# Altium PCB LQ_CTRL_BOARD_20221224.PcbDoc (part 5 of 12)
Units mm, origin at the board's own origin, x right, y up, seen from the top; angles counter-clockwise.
Board outline 260 x 142 mm, 6 copper layers (Top Layer, Mid-Layer 1, Mid-Layer 2, Mid-Layer 3, Mid-Layer 4, Bottom Layer); 1105 components, 1039 nets, 3898 pads, 1277 vias.
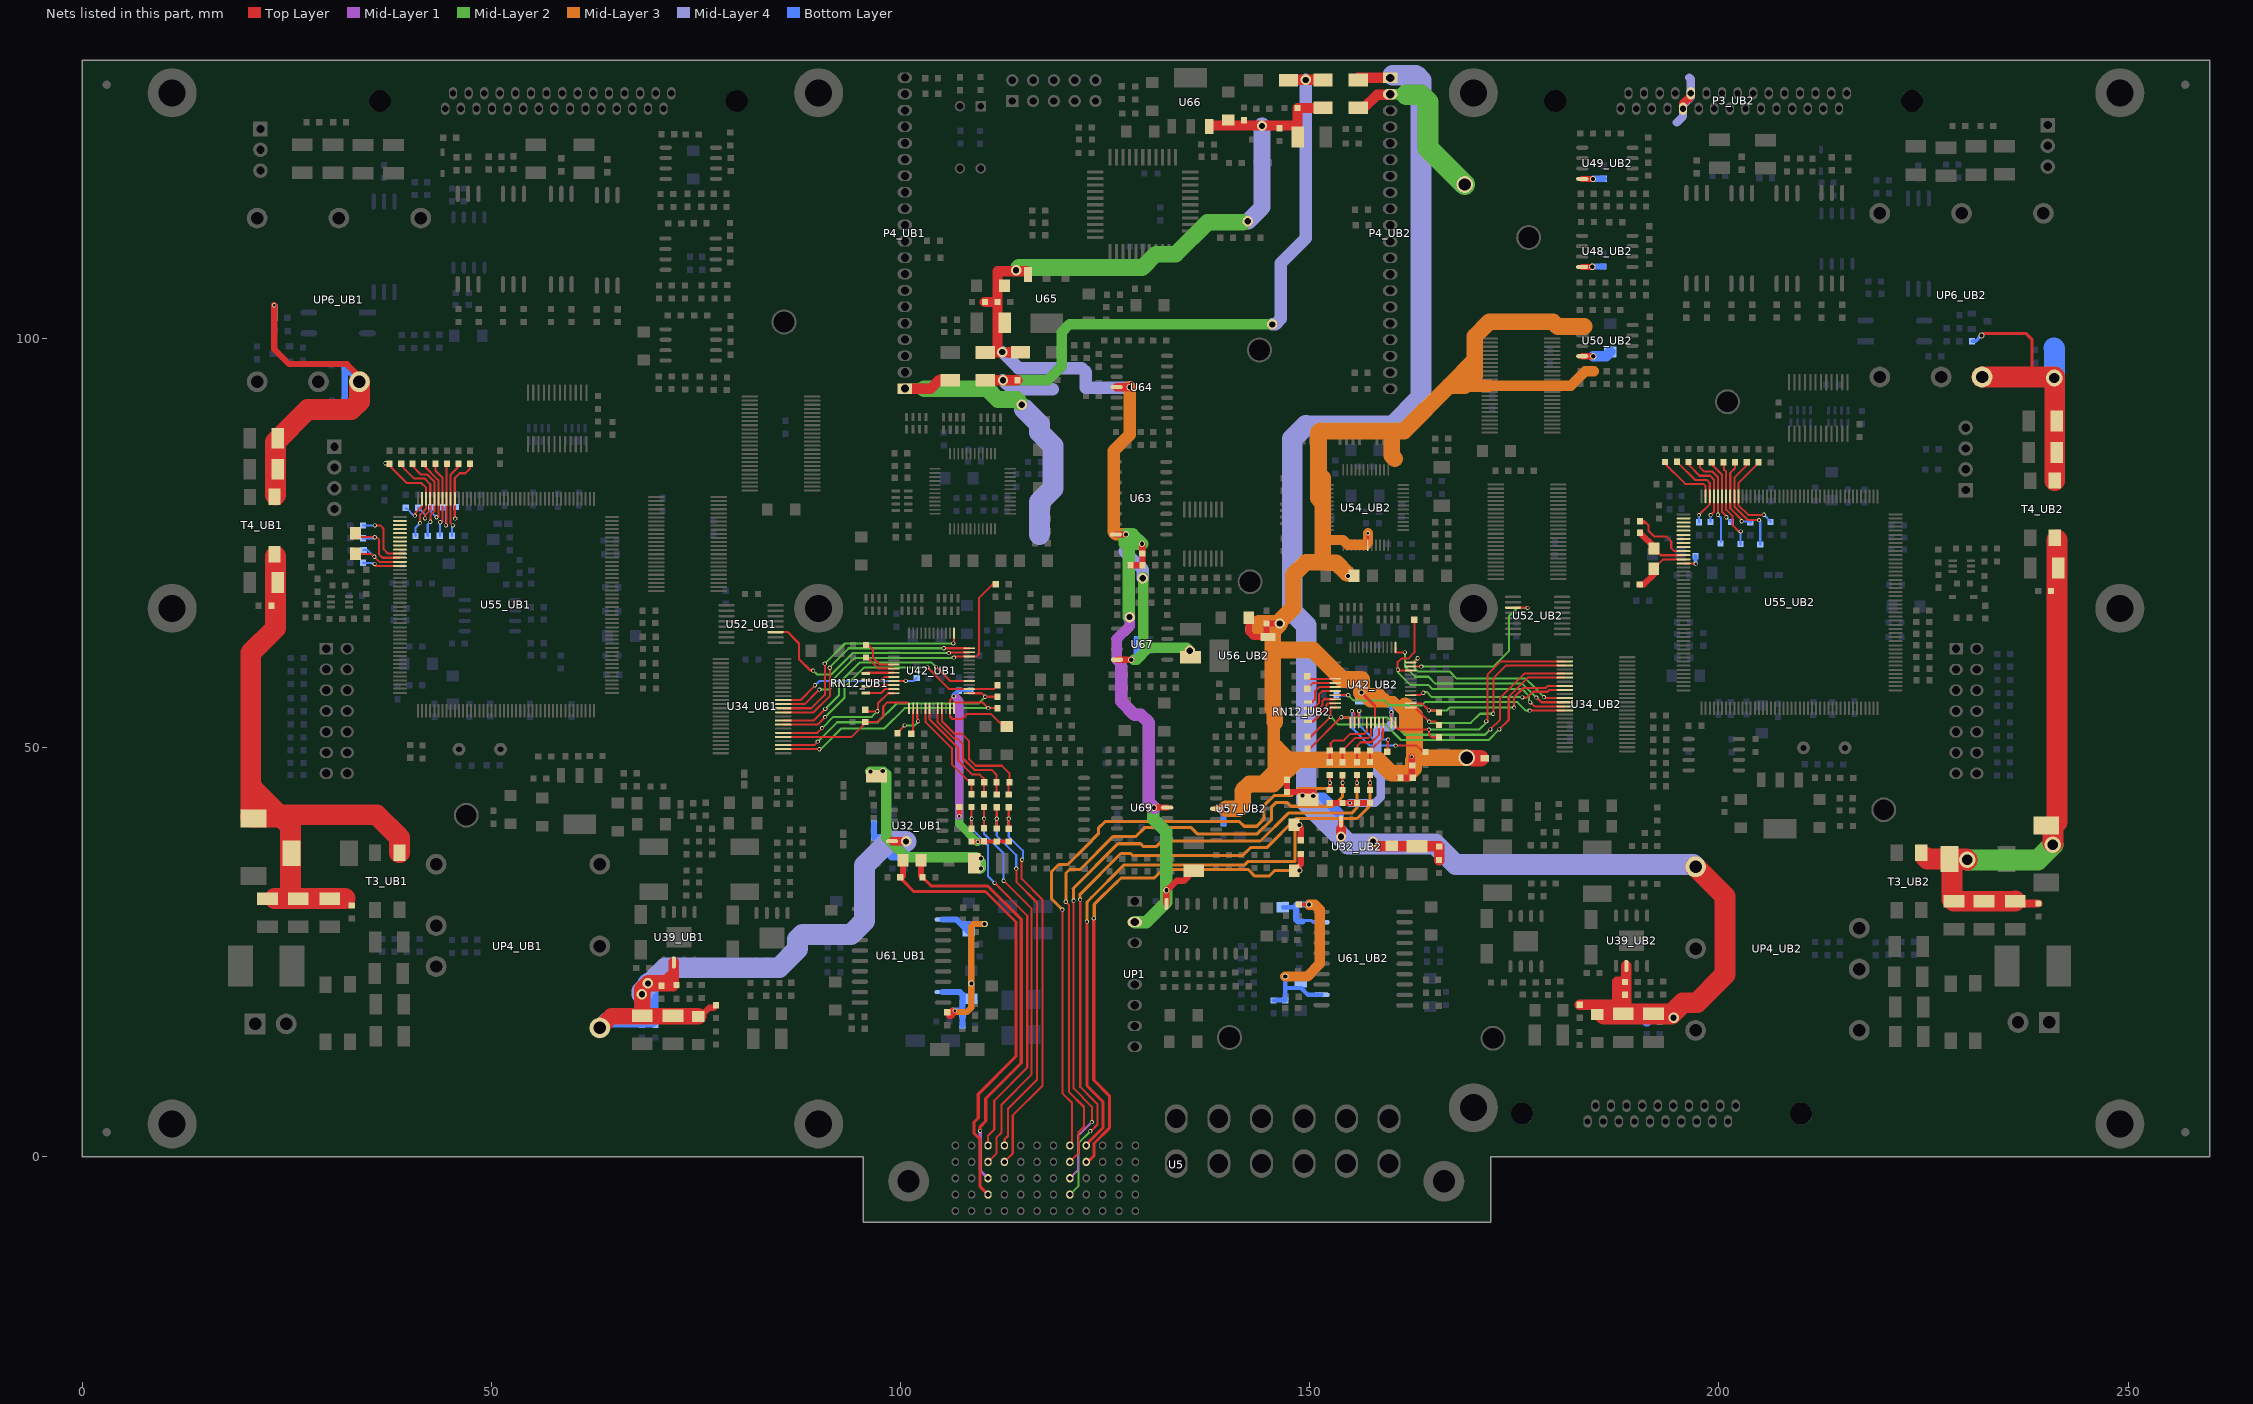
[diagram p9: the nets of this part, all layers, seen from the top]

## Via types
v1: diameter 0.508, hole 0.305, Top Layer to Bottom Layer, 845 vias
v2: diameter 0.762, hole 0.508, Top Layer to Bottom Layer, 317 vias
v3: diameter 1.27, hole 0.762, Top Layer to Bottom Layer, 77 vias
v4: diameter 2.032, hole 1.524, Top Layer to Bottom Layer, 15 vias
v5: diameter 2.032, hole 1.27, Top Layer to Bottom Layer, 11 vias
v6: diameter 1.27, hole 0.711, Top Layer to Bottom Layer, 8 vias
v7: diameter 2.54, hole 1.778, Top Layer to Bottom Layer, 3 vias
v8: diameter 1.524, hole 1.016, Top Layer to Bottom Layer, 1 vias

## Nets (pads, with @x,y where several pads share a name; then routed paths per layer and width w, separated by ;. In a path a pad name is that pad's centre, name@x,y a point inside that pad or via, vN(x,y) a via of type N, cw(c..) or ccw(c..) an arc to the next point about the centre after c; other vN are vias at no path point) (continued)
+5VA_UB2: C242_UB2.1 C284_UB2.1 C285_UB2.2 C311_UB2.1 C312_UB2.1 C327_UB2.1 C328_UB2.1 C373_UB2.1 C374_UB2.2 C393_UB2.1 C395_UB2.1 D28.1 P3_UB2.11 P3_UB2.26 P4_UB2.2 R203_UB2.1 R219_UB2.2 R229_UB2.2 R283_UB2.1 U42_UB2.43 U48_UB2.8 U49_UB2.8 U50_UB2.8 U54_UB2.43 U56_UB2.3 U57_UB2.4 | length 285.8
  Top Layer w0.254: C373_UB2.1@155.397,70.993 C373_UB2.1@155.397,71.17 ; v2(156.337,56.718) 157.984,55.072 U42_UB2.43@157.984,53.05 ; U54_UB2.43@157.092,74.723 157.092,75.978 157.074,75.996 157.074,76.123 v1(157.124,76.174) ; C242_UB2.1@162.535,47.803 162.535,46.361 R203_UB2.1@162.585,46.31
  Top Layer w0.762: U57_UB2.4@138.557,42.52 v2(139.776,42.52) ; C393_UB2.1@142.559,65.862 142.559,64.07 143.129,63.5 144.678,63.5 144.729,63.551 C395_UB2.1@144.729,65.151 146.325,65.151 v3@146.329,65.156 ; R219_UB2.2@160.985,46.31 162.484,46.31 162.535,46.361 162.484,46.412 v1(162.484,48.895) ; U48_UB2.8@183.286,108.717 184.511,108.717 v2(184.531,108.737) ; U50_UB2.8@183.312,97.815 v2(184.658,97.815) ; U49_UB2.8@183.312,119.482 v2(184.633,119.482)
  Top Layer w1.016: P3_UB2.26@195.621,128.047 195.621,128.685 196.573,129.637 P3_UB2.11@196.573,129.952
  Top Layer w1.27: D28.1@155.931,128.168 156.629,128.168 158.229,129.769 P4_UB2.2@159.646,129.769
  Top Layer w2.032: v4@169.875,48.692 R283_UB2.1@170.891,48.692
  Mid-Layer 2 w1.27: P4_UB2.2@159.842,129.826 161.766,129.826 161.823,129.769
  Mid-Layer 2 w2.54: 161.823,129.769 163.576,129.769 164.465,128.88 164.465,123.266 v4(168.935,118.796)
  Mid-Layer 3 w1.27: 151.587,75.362 154.051,75.362 154.635,74.778 156.896,74.778 157.124,75.006 v1(157.124,76.174) ; 159.309,55.677 160.198,55.677 161.544,54.331 161.544,52.426 162.814,51.156 ; 171.983,94.209 181.889,94.209 183.667,95.987 184.709,95.987
  Mid-Layer 3 w1.524: 143.916,45.542 145.618,47.244 145.618,50.241 ; 145.542,45.542 145.898,45.898 145.898,49.962 145.618,50.241 ; 145.721,53.087 145.618,52.984 145.618,50.241 ; 159.334,55.651 159.309,55.677 ; 168.935,94.209 171.983,94.209 ; 159.309,55.677 158.496,56.49 156.566,56.49 v2(156.337,56.718) 157.378,55.677 159.309,55.677
  Mid-Layer 3 w2.032: v2(139.776,42.52) 141.326,42.52 141.808,43.002 141.808,44.729 142.621,45.542 143.916,45.542 145.542,45.542 ; 143.104,64.44 143.815,65.151 145.491,65.151 ; 144.805,64.465 145.491,65.151 ; 145.721,53.087 145.721,54.482 145.593,54.61 145.542,54.61 145.466,54.686 145.466,61.62 ; 145.898,45.898 148.488,48.489 ; 145.898,49.962 147.371,48.489 148.488,48.489 ; 151.079,48.489 148.488,48.489 ; 151.587,82.931 151.587,79.934 ; v2@154.535,71.299 153.266,72.567 152.096,72.567 152.019,72.644 ; v2(156.337,56.718) 156.337,58.293 156.362,58.318 154.026,58.318 150.422,61.922 145.768,61.922 145.466,61.62 ; 160.401,85.268 160.02,85.649 160.02,88.671 ; 161.696,55.067 162.814,53.95 162.814,51.156 162.814,48.895 162.941,48.768 v4(169.189,48.768) 163.043,48.768 162.687,48.412 162.687,47.422 162.103,46.838 160.02,46.838 158.369,48.489 148.488,48.489 ; 170.18,97.384 170.18,97.333 ; 183.566,101.448 180.289,101.448 179.73,102.006 171.933,102.006 170.18,100.254 170.18,97.333 ; 145.466,61.62 145.466,64.262 ; 145.466,64.262 v3(146.355,65.151) v3@146.075,65.151 ; 145.466,64.262 145.466,64.541 v3@146.075,65.151 ; 145.491,65.151 v3@146.075,65.151 ; v3@146.075,65.151 147.98,67.056 147.98,71.095 149.53,72.644 152.019,72.644 ; 151.587,79.934 151.587,75.362 151.587,73.076 152.019,72.644 ; 151.587,79.934 151.079,80.442 151.079,88.519 151.232,88.671 160.02,88.671 ; 160.02,88.671 161.519,88.671 167.056,94.209 ; 167.056,94.209 170.18,97.333 ; 167.056,94.209 168.935,94.209 170.18,95.453 170.18,97.333
  Mid-Layer 4 w1.016: 194.869,126.365 195.621,127.117 P3_UB2.26@195.621,128.047 195.621,128.54 196.573,129.492 P3_UB2.11@196.573,129.952 196.573,131.671 196.367,131.877
  Bottom Layer w0.762: C327_UB2.1@139.471,40.73 139.471,42.215 v2(139.776,42.52) 141.351,42.52 C284_UB2.1@141.427,42.596 ; C328_UB2.1@154.381,57.836 154.635,57.582 155.905,57.582 156.312,57.175 C312_UB2.1@156.312,56.007 ; v2(184.531,108.737) 184.556,108.763 C374_UB2.2@185.903,108.763 ; v2(184.633,119.482) 184.658,119.507 C285_UB2.2@185.928,119.507
  Bottom Layer w1.27: v2(184.658,97.815) 186.221,97.815 186.741,98.336 C311_UB2.1@186.741,98.349
  other v2: 154.686,70.967
+5VMS: C3.1 C4.1 C428.1 C429.1 C430.1 C431.1 C432.1 C434.1 C436.1 C438.1 C444.1 D27.2 D28.2 DR4.1 LED17.1 R399.1 R406.2 U2.8 U63.16 U64.4 U65.3 U66.3 U69.4 UP1.2 | length 194.2
  Top Layer w0.762: U63.16@126.314,76.022 127.305,76.022 v2@127.33,76.048 ; R406.2@128.092,72.259 129.544,72.259 R399.1@129.56,72.275 129.56,73.697 C444.1@129.535,73.723 129.535,74.823 v2@129.54,74.828 ; v2@130.962,42.672 130.975,42.659 U69.4@132.593,42.659 ; v2@132.486,32.614 132.486,30.912 U2.8@132.512,30.886 132.512,32.639 132.664,32.639 133.756,33.731 134.645,33.731 C3.1@135.839,34.925
  Top Layer w1.016: U64.4@126.416,94.031 127.914,94.031 127.94,94.056 127.965,94.031 v2(127.991,94.031)
  Top Layer w1.27: C434.1@110.312,104.445 C430.1@111.851,104.445 ; D27.2@110.37,98.273 v3@111.912,98.273 ; 111.851,107.899 C430.1@111.851,104.445 ; 111.862,108.204 U65.3@115.403,108.204 ; 113.36,98.222 113.309,98.273 ; DR4.1@114.656,98.298 113.335,98.298 113.309,98.273 ; U66.3@138.125,126.009 148.336,126.009 148.514,126.187 ; C428.1@148.539,124.612 148.514,124.638 148.514,126.187 ; D28.2@151.631,128.168 151.605,128.143 LED17.1@148.514,128.143 148.514,126.187 ; C430.1@111.851,104.445 111.851,98.334 v3@111.912,98.273 ; v3@111.912,98.273 113.309,98.273
  Mid-Layer 1 w1.27: 126.975,59.868 126.975,60.173 126.441,60.706 126.441,63.297 127.991,64.846 v3(127.991,65.938)
  Mid-Layer 1 w1.524: 126.975,59.868 126.975,55.631 128.605,54 129.388,54 130.353,53.035 130.353,43.282 v2(130.988,42.647)
  Mid-Layer 2 w1.524: v3@127.889,65.938 127.889,74.905 ; UP1.2@128.626,28.677 130.048,28.677 132.486,31.115 132.486,39.675 130.912,41.25 130.912,42.57 v2(130.988,42.647) ; 127.432,74.93 127.432,75.921 v2(127.559,76.048) 128.372,76.048 v2(129.515,74.905) 127.457,74.905 127.432,74.93
  Mid-Layer 2 w2.032: v3@114.44,108.648 129.553,108.648 131.191,110.287 133.629,110.287 137.516,114.173 v3@141.834,114.173
  Mid-Layer 3 w1.524: v2(127.559,76.048) 126.34,76.048 126.035,76.352 126.035,86.258 127.991,88.214 v2(127.991,94.031)
  Mid-Layer 4 w1.524: v3(112.446,98.323) 114.402,96.368 122.149,96.368 122.657,95.86 122.657,93.955 127.914,93.955 v2(127.991,94.031)
  Mid-Layer 4 w2.032: v3@142.456,114.287 144.17,116.002 v3(144.17,125.959)
  Bottom Layer w0.762: UP1.2@128.575,28.626 UP1.2@128.626,28.677 130.429,28.677 131.191,29.439 C4.1@131.191,29.667
  other v2: 132.486,32.563
  other v3: 114.122,108.331 142.443,114.3
+12V_UB1: C16_UB1.1 C233_UB1.1 C234_UB1.2 C235_UB1.2 C263_UB1.1 C264_UB1.2 C286_UB1.1 C287_UB1.1 C288_UB1.1 C289_UB1.1 C377_UB1.1 C378_UB1.1 C379_UB1.1 D25.1 LED9_UB1.1 P4_UB1.1 R236_UB1.1 U32_UB1.8 U39_UB1.2 UP4_UB1.3 | length 152.2
  Top Layer w0.762: C263_UB1.1@75.311,17.145 75.565,17.145 76.632,18.212 77.165,18.212 LED9_UB1.1@77.47,18.517
  Top Layer w1.016: U32_UB1.8@98.973,38.557 v3@100.381,38.557
  Top Layer w1.27: 71.577,21.793 72.085,22.301 ; R236_UB1.1@72.263,20.828 72.314,20.879 U39_UB1.2@72.314,23.749 ; P4_UB1.1@100.533,93.853 103.708,93.853 104.826,94.971 ; D25.1@105.842,94.869 D25.1@106.07,94.869
  Top Layer w2.032: UP4_UB1.3@63.262,15.745 64.662,17.145 C263_UB1.1@75.311,17.145 ; C16_UB1.1@68.453,17.221 68.453,20.472 69.19,21.209 71.806,21.209
  Mid-Layer 2 w1.27: v2(96.317,47.066) 97.917,47.066 98.247,46.736 98.247,39.014 100.686,36.576 109.22,36.576 109.83,35.966 v2(109.83,35.23) ; P4_UB1.1@100.533,93.853 102.921,93.853
  Mid-Layer 2 w2.032: 102.921,93.853 110.56,93.853 111.881,92.532 114.198,92.532 v3@114.529,92.202
  Mid-Layer 4 w2.54: v3(68.402,19.863) 68.402,20.218 71.272,23.089 85.141,23.089 87.427,25.375 87.427,26.568 88.011,27.153 93.955,27.153 95.606,28.804 95.606,35.585 98.552,38.532 v3(100.686,38.532) ; 115.164,91.338 116.992,89.51 116.992,88.519 118.643,86.868 118.643,81.661 116.992,80.01 116.992,76.048
  Bottom Layer w0.762: C287_UB1.1@96.774,40.716 C286_UB1.1@96.774,39.04 99.898,39.04 v3@100.381,38.557
  Bottom Layer w1.27: C377_UB1.1@98.984,36.805 C378_UB1.1@100.508,36.805 100.508,38.43 v3@100.381,38.557
  Bottom Layer w2.032: UP4_UB1.3@63.262,15.745 63.268,15.745 64.338,16.815 69.52,16.815
  Bottom Layer w2.54: 69.139,17.17 v3(69.139,21.184)
  other v2: 109.823,36.437 97.841,47.117
  other v3: 114.808,91.872
+12V_UB2: C16_UB2.1 C233_UB2.1 C234_UB2.2 C235_UB2.2 C263_UB2.1 C264_UB2.2 C286_UB2.1 C287_UB2.1 C288_UB2.1 C289_UB2.1 C377_UB2.1 C378_UB2.1 C379_UB2.1 D26.1 LED9_UB2.1 P4_UB2.1 R236_UB2.1 U32_UB2.8 U39_UB2.2 UP4_UB2.3 | length 251.6
  Top Layer w0.762: C377_UB2.1@147.244,46.076 C378_UB2.1@147.244,44.552 150.495,44.552 150.52,44.526 150.52,44.348 C379_UB2.1@149.784,43.612 ; 153.822,40.03 U32_UB2.8@153.822,40.97
  Top Layer w1.27: v3(153.822,39.091) 153.822,40.03 ; D26.1@155.931,131.826 P4_UB2.1@159.842,131.826 ; v3@157.785,38.456 158.318,37.922 C289_UB2.1@160.096,37.922 ; C289_UB2.1@160.02,37.998 C289_UB2.1@160.096,37.922 ; C286_UB2.1@165.811,36.246 165.811,37.897 C287_UB2.1@165.837,37.922 C288_UB2.1@163.119,37.922 C289_UB2.1@160.096,37.922 ; LED9_UB2.1@183.007,18.567 187.122,18.567 ; C263_UB2.1@185.191,17.45 186.004,17.45 187.122,18.567 ; C16_UB2.1@188.316,17.45 188.697,17.831 188.697,19.152 ; R236_UB2.1@188.519,21.361 187.604,21.361 187.604,19.05 187.122,18.567 ; U39_UB2.2@188.697,23.317 188.697,19.152 ; 187.122,18.567 188.112,18.567 188.697,19.152
  Top Layer w2.54: 186.004,17.45 C16_UB2.1@188.316,17.45 C233_UB2.1@192.024,17.45 194.234,17.45 195.605,18.821 197.333,18.821 200.762,22.25 200.762,31.825 UP4_UB2.3@197.15,35.436
  Mid-Layer 4 w2.54: P4_UB2.1@160.198,132.156 161.62,132.156 ; UP4_UB2.3@197.15,35.436 196.874,35.712 167.843,35.712 165.329,38.227 154.686,38.227 v3(153.822,39.091) 149.581,43.332 149.581,64.907 147.879,66.608 147.879,87.706 149.555,89.383 149.631,89.306 160.147,89.306 163.601,92.761 163.601,130.175 ; 161.62,132.156 163.601,130.175 ; 161.62,132.156 162.97,132.156 163.601,131.525 163.601,130.175
  Bottom Layer w0.762: 153.213,40.64 153.213,41.758 151.435,43.536 149.174,43.536 149.123,43.586 v2(149.123,44.145) 151.74,44.145 153.822,42.062 153.822,40.03 ; 153.213,40.64 153.822,40.03 ; 153.213,40.64 153.213,39.7 v3(153.822,39.091) 153.822,40.03
  Bottom Layer w1.27: C235_UB2.2@191.186,16.535 191.186,16.916 v3@194.107,16.916
  other v2: 150.444,44.094
  other v3: 194.462,16.993 157.734,38.481
+12VMS: C424.1 C425.1 C426.1 D25.2 D26.2 DR3.1 LED16.1 U67.8 | length 109.9
  Top Layer w0.762: U67.8@126.461,60.731 v2(128.194,60.731)
  Top Layer w1.27: D25.2@110.37,94.869 v3(112.522,94.869) LED16.1@114.3,94.869 ; C424.1@135.204,61.57 135.433,61.341 C424.1@135.433,61.011 ; DR3.1@148.285,131.521 148.336,131.572 v3(149.53,131.572) D26.2@151.631,131.572
  Mid-Layer 2 w1.27: v3(112.522,94.869) 118.008,94.869 119.71,96.571 119.71,100.762 120.65,101.702 138.684,101.702 ; v2@128.473,60.731 128.854,60.731 130.302,62.179 ; v3@129.642,70.79 129.642,62.84 130.302,62.179 ; v3(135.357,61.824) 135.001,62.179 130.302,62.179 ; 138.709,101.727 138.684,101.702 ; v3(145.415,101.702) 138.684,101.702
  Mid-Layer 4 w1.524: v3(112.522,94.869) 113.614,93.777 118.593,93.777 ; 127.381,73.965 129.616,71.73 v3(129.616,70.688) ; v3(145.415,101.702) 145.796,101.702 146.456,102.362 146.456,109.169 149.53,112.243 v3(149.53,131.572)
  Bottom Layer w0.762: v2(128.194,60.731) 128.473,60.731 128.88,61.138 C425.1@128.88,63.246
+28V_UB1: C214_UB1.1 C221_UB1.1 C222_UB1.1 C223_UB1.1 C276_UB1.1 C277_UB1.2 D13_UB1.2 DR2_UB1.1 T3_UB1.4 T4_UB1.2 | length 82.1
  Top Layer w2.54: D13_UB1.2@20.584,41.504 24.333,41.504 24.054,41.783 ; 20.599,46.126 20.599,42.545 21.361,41.783 24.054,41.783 ; 20.599,46.203 20.599,61.544 23.627,64.572 T4_UB1.2@23.627,73.381 ; 20.828,45.136 20.828,45.009 24.054,41.783 ; C222_UB1.1@23.546,31.547 C221_UB1.1@26.416,31.547 C223_UB1.1@30.251,31.547 32.121,31.547 ; 24.496,41.341 25.146,40.691 25.146,41.783 ; C221_UB1.1@25.451,31.521 25.451,40.665 ; T3_UB1.4@38.789,37.15 38.789,38.986 35.992,41.783 25.146,41.783 ; 24.054,41.783 25.146,41.783
+28V_UB2: C214_UB2.1 C221_UB2.1 C222_UB2.1 C223_UB2.1 C276_UB2.1 C277_UB2.2 D13_UB2.2 DR2_UB2.1 T3_UB2.4 T4_UB2.2 | length 69.3
  Top Layer w1.016: C221_UB2.1@236.22,31.242 236.525,30.937 C277_UB2.2@239.039,30.937
  Top Layer w2.54: T3_UB2.4@225.294,36.572 225.494,36.373 DR2_UB2.1@228.168,36.373 DR2_UB2.1@228.473,36.373 ; v5(230.327,36.271) 230.226,36.373 DR2_UB2.1@228.473,36.373 ; C221_UB2.1@236.22,31.242 236.195,31.217 C222_UB2.1@228.727,31.217 228.473,31.471 DR2_UB2.1@228.473,36.373 ; v5@240.868,38.354 240.843,38.379 240.843,40.401 241.325,40.884 T4_UB2.2@241.325,75.352
  Mid-Layer 2 w2.54: v5(230.327,36.271) 238.963,36.271 v5(240.817,38.125)
+28VB_UB1: C269_UB1.2 C270_UB1.1 C271_UB1.1 C272_UB1.2 R256_UB1.2 T4_UB1.1 UP6_UB1.2 | length 47.4
  Top Layer w0.762: v1(23.47,104.038) 23.47,98.679 25.298,96.85 32.334,96.85 33.885,95.299 UP6_UB1.2@33.885,94.691
  Top Layer w2.54: T4_UB1.1@23.622,80.848 23.622,87.325 27.584,91.288 ; 27.61,91.313 27.584,91.288 ; UP6_UB1.2@33.885,94.691 33.885,92.28 32.893,91.288 27.584,91.288
  Bottom Layer w0.762: v1(23.47,104.038) 23.495,104.013 R256_UB1.2@23.495,102.514 ; C269_UB1.2@32.055,96.698 32.106,96.647 C269_UB1.2@32.106,96.471 ; C272_UB1.2@32.106,92.405 C269_UB1.2@32.106,96.471 ; UP6_UB1.2@33.885,94.691 C269_UB1.2@32.106,96.471
+28VB_UB2: C269_UB2.2 C270_UB2.1 C271_UB2.1 C272_UB2.2 R256_UB2.2 T4_UB2.1 UP6_UB2.2 | length 37.8
  Top Layer w0.381: v2(232.08,100.355) 232.334,100.609 237.49,100.609 238.277,99.822 238.277,95.275
  Top Layer w2.54: UP6_UB2.2@232.158,95.275 238.277,95.275 241.051,95.275 T4_UB2.1@241.051,82.626
  Bottom Layer w0.381: R256_UB2.2@230.937,99.644 231.369,99.644 v2(232.08,100.355)
  Bottom Layer w2.54: 240.944,98.806 240.995,98.755 v5(240.995,95.148)
+CAN5V_UB1: C11_UB1.1 C410_UB1.1 C411_UB1.1 C412_UB1.1 LED15_UB1.1 U61_UB1.12 U61_UB1.19 | length 31.2
  Top Layer w0.762: 105.918,17.196 106.172,17.196 106.401,17.424 v1@106.401,17.856
  Mid-Layer 3 w0.762: v1@106.401,17.856 106.578,17.678 108.102,17.678 108.636,18.212 108.636,20.98 108.636,28.169 108.89,28.423 v2(110.287,28.423)
  Bottom Layer w0.762: U61_UB1.19@105.161,20.117 107.239,20.117 107.564,19.792 C410_UB1.1@107.564,17.475 ; U61_UB1.12@105.161,28.981 106.858,28.981 107.417,28.423 ; v1(106.604,17.856) 107.386,17.856 ; 107.183,17.856 C410_UB1.1@107.564,17.475 ; C412_UB1.1@107.564,16.027 C410_UB1.1@107.564,17.475 ; C410_UB1.1@107.589,17.45 C410_UB1.1@107.564,17.475 ; C11_UB1.1@108.356,27.483 107.417,28.423 ; C411_UB1.1@108.636,19.329 v2@108.636,20.98 ; v2(110.287,28.423) 107.417,28.423
  other v2: 108.661,21.158
+CAN5V_UB2: C11_UB2.1 C410_UB2.1 C411_UB2.1 C412_UB2.1 LED15_UB2.1 U61_UB2.12 U61_UB2.19 | length 32.7
  Top Layer w0.381: LED15_UB2.1@148.655,30.81 v2(149.936,30.81)
  Mid-Layer 3 w1.27: v2(147.015,22.022) 149.682,22.022 151.232,23.571 151.232,30.175 150.597,30.81 v2(149.936,30.81)
  Bottom Layer w0.381: 149.115,28.736 149.233,28.854 150.241,28.854 150.444,28.651 U61_UB2.19@151.449,28.651
  Bottom Layer w0.508: C412_UB2.1@145.567,19.101 C410_UB2.1@147.015,19.101 147.015,20.625 ; 145.974,19.177 C410_UB2.1@146.724,19.177 ; C11_UB2.1@146.736,30.48 148.045,30.48 148.325,30.201 ; 146.964,20.625 147.015,20.625 ; v2(147.015,22.022) 147.015,20.625 ; 149.115,28.736 149.123,28.727 ; U61_UB2.12@151.449,19.787 149.809,19.787 148.971,20.625 147.015,20.625
  Bottom Layer w0.762: 149.115,28.736 148.607,28.736 148.361,28.981 148.361,30.164 148.325,30.201 148.325,30.672 148.463,30.81 v2(149.936,30.81)
A_COS+: R217_UB1.1 R220_UB1.2 U5.D4 | length 48.2
  Top Layer w0.254: U5.D4@112.7,-0.627 113.716,0.389 113.716,5.055 117.348,8.687 117.348,31.414 114.808,33.954 v1@114.808,36.297 ; R217_UB1.1@113.222,42.697 113.233,42.687 v1(113.233,41.326) R220_UB1.2@113.233,40.081
  Bottom Layer w0.254: v1(113.233,41.326) 113.233,39.116 114.96,37.389 v1@114.96,36.398
  other v1: 114.859,36.297
A_COS+'_UB1: C251_UB1.2 R217_UB1.2 U42_UB1.45 | length 16.4
  Top Layer w0.254: U42_UB1.45@105.049,54.785 105.049,53.242 106.602,51.689 107.467,51.689 108.382,50.775 108.382,48.571 109.176,47.777 112.395,47.777 113.309,46.863 C251_UB1.2@113.309,45.745 113.222,45.658 R217_UB1.2@113.222,44.272
A_COS+'_UB2: C251_UB2.2 R217_UB2.2 U42_UB2.45 | length 5.7
  Top Layer w0.254: R217_UB2.2@157.378,48.082 C251_UB2.2@157.378,49.649 157.421,49.649 158.984,51.211 U42_UB2.45@158.984,53.05
A_COS+_UB2: R217_UB2.1 R220_UB2.2 U5.B8 | length 83.8
  Top Layer w0.254: v1@121.971,31.42 121.971,8.534 123.406,7.099 124.079,6.426 124.079,3.937 123.266,3.124 v1(123.215,3.124) ; R220_UB2.2@157.378,44.798 R217_UB2.1@157.378,46.66
  Mid-Layer 2 w0.254: U5.B8@120.7,-4.627 121.742,-3.585 121.742,1.651 v1(123.215,3.124)
  Mid-Layer 3 w0.381: v1(121.945,31.42) 121.945,32.08 126.924,37.059 128.118,37.059 128.359,36.817 141.821,36.817 142.773,37.77 144.755,37.77 148.311,41.326 155.804,41.326 157.391,42.913 v1(157.391,45.72)
A_COS-: R225_UB1.2 R228_UB1.1 U5.E4 | length 46.5
  Top Layer w0.254: R228_UB1.1@111.749,42.697 111.76,42.687 v1(111.76,41.3) R225_UB1.2@111.76,40.107 ; U5.E4@112.878,1.55 U5.E4@112.7,1.373 112.7,2.108 113.132,2.54 113.132,5.842 116.688,9.398 116.688,31.064 114.198,33.553 114.198,35.027 v1@114.021,35.204
  Bottom Layer w0.254: v1(111.76,41.3) 111.76,39.243 114.148,36.855 v1(114.148,35.204)
A_COS-'_UB1: C251_UB1.1 R228_UB1.2 U42_UB1.44 | length 15
  Top Layer w0.254: U42_UB1.44@104.549,54.785 104.549,53.095 106.565,51.079 106.985,51.079 107.645,50.419 107.645,48.661 109.043,47.263 111.157,47.263 111.735,46.685 C251_UB1.1@111.735,45.745 111.749,45.731 R228_UB1.2@111.749,44.272
A_COS-'_UB2: C251_UB2.1 R228_UB2.2 U42_UB2.44 | length 6.9
  Top Layer w0.254: R228_UB2.2@155.778,48.057 155.778,49.624 C251_UB2.1@155.804,49.649 155.829,49.675 155.829,50.241 156.235,50.648 157.556,50.648 158.484,51.575 U42_UB2.44@158.484,53.05
A_COS-_UB2: R225_UB2.2 R228_UB2.1 U5.C8 | length 82.5
  Top Layer w0.254: v1(121.158,31.293) 121.158,8.357 123.393,6.121 v1(123.393,4.242) ; R225_UB2.2@155.778,44.806 R228_UB2.1@155.778,46.634
  Mid-Layer 1 w0.254: U5.C8@120.7,-2.627 121.717,-1.61 121.717,2.565 ; 122.111,2.959 121.717,2.565 ; v1(123.393,4.242) 121.717,2.565
  Mid-Layer 3 w0.381: 121.082,32.766 121.158,32.842 ; v1(121.158,31.293) 121.158,32.842 ; 121.526,33.21 121.158,32.842 ; v1(155.766,45.695) 155.766,42.608 155.143,41.986 147.396,41.986 143.993,38.583 131.928,38.583 131.242,37.897 129.692,37.897 129.35,38.24 126.555,38.24 121.158,32.842
A_E\X\C\_UB1: C248_UB1.2 U42_UB1.39 | length 4.9
  Top Layer w0.254: C248_UB1.2@99.644,51.74 99.644,51.841 v1(100.508,52.705) ; U42_UB1.39@102.049,54.785 102.049,53.552 102.159,53.442 v1(102.159,53.188)
  Mid-Layer 2 w0.254: v1(100.508,52.705) 101.727,52.705 102.184,53.162 v1(102.159,53.188)
A_E\X\C\_UB2: C248_UB2.2 U42_UB2.39 | length 9
  Top Layer w0.254: U42_UB2.39@155.984,53.05 155.984,54.395 v1(156.058,54.469) ; C248_UB2.2@159.537,49.454 159.537,50.927 v1(159.588,50.978)
  Bottom Layer w0.254: v1(156.058,54.469) 156.058,52.73 157.81,50.978 v1(159.588,50.978)
A_EXC_UB1: C225_UB1.2 U42_UB1.38 | length 3.2
  Top Layer w0.254: C225_UB1.2@101.321,51.689 101.549,51.917 U42_UB1.38@101.549,54.785
A_EXC_UB2: C225_UB2.2 U42_UB2.38 | length 13.5
  Top Layer w0.254: v1@155.143,54.432 155.484,54.092 U42_UB2.38@155.484,53.05 ; v1(160.503,50.241) 163.068,50.241 C225_UB2.2@163.855,49.454
  Bottom Layer w0.254: v1(155.169,54.458) 155.169,52.4 157.328,50.241 v1(160.503,50.241)
A_EXCN: C250_UB1.1 R216_UB1.1 U5.B3 | length 55.3
  Top Layer w0.381: R216_UB1.1@100.305,34.301 100.203,34.199 100.203,33.833 101.625,32.41 110.388,32.41 114.122,28.677 114.122,12.268 109.499,7.645 109.499,4.724 108.966,4.191 108.966,2.896 109.728,2.134 109.728,-3.655 ; 109.728,-3.2 109.728,-3.655 ; U5.B3@110.7,-4.627 109.728,-3.655
  Top Layer w0.762: R216_UB1.1@100.058,34.054 R216_UB1.1@100.203,34.199 ; R216_UB1.1@100.305,34.301 C250_UB1.1@100.305,36.22
A_EXCN_UB2: C250_UB2.1 R216_UB2.1 U5.E9 | length 66.2
  Top Layer w0.381: U5.E9@122.7,1.373 122.7,1.491 124.739,3.531 124.739,6.731 122.784,8.687 v1(122.784,28.727)
  Top Layer w0.762: C250_UB2.1@148.082,40.589 148.463,40.589 148.895,40.157 R216_UB2.1@148.895,38.659
  Mid-Layer 3 w0.381: v1(122.784,28.727) 122.784,31.115 123.215,31.547 ; 123.355,31.686 123.215,31.547 ; v2(148.742,40.538) 148.184,39.98 148.184,36.093 142.494,36.093 142.062,35.662 127.33,35.662 123.215,31.547
A_EXCP: C224_UB1.1 R198_UB1.2 U5.C3 | length 51.2
  Top Layer w0.381: R198_UB1.2@102.692,34.163 103.784,33.071 110.693,33.071 114.757,29.007 114.757,11.455 110.414,7.112 110.414,4.369 109.728,3.683 v1(109.728,3.15)
  Top Layer w0.762: C224_UB1.1@102.504,36.246 102.504,34.352 R198_UB1.2@102.692,34.163
  Mid-Layer 1 w0.381: 109.753,-1.016 109.753,-1.681 ; v1@109.753,3.251 109.753,-1.681 ; U5.C3@110.7,-2.627 109.753,-1.681
A_EXCP_UB2: C224_UB2.1 R198_UB2.2 U5.D9 | length 63.7
  Top Layer w0.381: U5.D9@122.7,-0.627 122.893,-0.627 123.647,0.127 123.647,1.612 125.527,3.492 125.527,7.468 123.622,9.373 v1(123.622,29.116)
  Top Layer w0.762: C224_UB2.1@148.107,34.95 148.92,35.763 R198_UB2.2@148.92,36.982
  Mid-Layer 3 w0.381: v1@123.673,29.159 123.673,30.836 126.467,33.63 126.517,33.63 ; 126.238,33.35 126.949,34.061 131.015,34.061 131.559,34.606 131.559,34.608 132.029,35.077 142.519,35.077 143.307,34.29 145.034,34.29 145.72,34.976 v2(148.768,34.976)
A_RDC_A0_UB1: R280_UB1.1 U34_UB1.5 U42_UB1.37 | length 18.2
  Top Layer w0.254: U34_UB1.5@85.674,51.301 85.681,51.308 94.031,51.308 R280_UB1.1@95.58,52.857 ; R280_UB1.1@95.707,53.111 97.13,53.111 97.892,53.873 97.892,55.016 98.4,55.524 100.838,55.524 101.049,55.314 U42_UB1.37@101.049,54.785
A_RDC_A0_UB2: R280_UB2.1 U34_UB2.5 U42_UB2.37 | length 40.3
  Top Layer w0.254: R280_UB2.1@149.733,49.86 149.987,49.86 153.822,53.696 v1(153.873,53.696) 154.915,53.696 154.984,53.627 U42_UB2.37@154.984,53.05 ; v1(172.085,52.222) 173.279,53.416 173.279,56.083 176.232,59.036 U34_UB2.5@181.178,59.036
  Mid-Layer 2 w0.254: v1(153.873,53.696) 159.487,53.696 161.62,51.562 171.425,51.562 v1(172.085,52.222)
A_RDC_A1_UB1: R281_UB1.1 U34_UB1.6 U42_UB1.36 | length 17.5
  Top Layer w0.254: U34_UB1.6@85.674,51.801 89.851,51.801 v1(90.424,52.375) ; R281_UB1.1@95.773,54.419 97.244,54.419 97.244,55.385 98.494,56.635 U42_UB1.36@99.199,56.635
  Mid-Layer 2 w0.254: v1(90.424,52.375) 91.796,53.746 96.495,53.746 v1(97.18,54.432)
A_RDC_A1_UB2: R281_UB2.1 U34_UB2.6 U42_UB2.36 | length 41.8
  Top Layer w0.254: R281_UB2.1@149.733,51.359 150.165,51.359 v1(152.552,53.746) 152.552,54.889 152.563,54.9 U42_UB2.36@153.134,54.9 ; v1(173.177,52.222) 174.32,53.365 ; 174.32,55.016 174.32,53.365 ; U34_UB2.6@181.178,58.536 176.65,58.536 174.32,56.206 174.32,53.365
  Mid-Layer 2 w0.254: v1(152.552,53.746) 153.492,52.807 159.283,52.807 161.163,50.927 171.882,50.927 v1(173.177,52.222)
A_RDC_A_UB1: R279_UB1.1 U42_UB1.29 | length 5
  Top Layer w0.254: R279_UB1.1@95.773,62.535 96.049,62.535 96.647,61.937 96.647,60.984 97.496,60.135 U42_UB1.29@99.199,60.135
A_RDC_A_UB2: R279_UB2.1 U42_UB2.29 | length 3.6
  Top Layer w0.254: R279_UB2.1@149.708,58.699 150.007,58.4 U42_UB2.29@153.134,58.4
A_RDC_B_UB1: R278_UB1.1 U42_UB1.30 | length 4
  Top Layer w0.254: R278_UB1.1@95.773,61.011 96.012,61.011 96.19,60.833 96.19,60.795 97.35,59.635 U42_UB1.30@99.199,59.635
A_RDC_B_UB2: R278_UB2.1 U42_UB2.30 | length 3.7
  Top Layer w0.254: R278_UB2.1@149.708,57.175 150.432,57.9 U42_UB2.30@153.134,57.9
A_RDC_CS_UB1: R290_UB1.1 U34_UB1.8 U42_UB1.2 | length 31.1
  Top Layer w0.254: U34_UB1.8@85.674,52.801 89.86,52.801 v1(90.78,53.721) ; v1(103.302,59.792) 105.959,57.135 U42_UB1.2@108.399,57.135 111.378,57.135 R290_UB1.1@111.851,57.607
  Mid-Layer 2 w0.254: v1(90.78,53.721) 93.167,56.109 93.167,57.404 95.555,59.792 v1(103.302,59.792)
A_RDC_CS_UB2: R290_UB2.1 U34_UB2.8 U42_UB2.2 | length 23.3
  Top Layer w0.254: U42_UB2.2@162.334,55.4 163.701,55.4 v1(164.574,54.526) R290_UB2.1@165.811,54.526 ; v1@174.955,54.864 174.955,56.109 176.124,57.277 178.816,57.277 179.075,57.536 ; 179.908,57.536 179.075,57.536 ; U34_UB2.8@181.178,57.536 179.075,57.536
  Mid-Layer 2 w0.254: v1(164.574,54.526) 166.743,54.526 167.107,54.889 v1(174.981,54.889)
A_RDC_DIR_UB1: RN12_UB1.5 U42_UB1.32 | length 3.6
  Top Layer w0.254: RN12_UB1.5@95.747,58.254 97.675,58.254 98.056,58.635 U42_UB1.32@99.199,58.635
A_RDC_DIR_UB2: RN12_UB2.5 U42_UB2.32 | length 4.9
  Top Layer w0.254: RN12_UB2.5@149.784,54.781 150.489,54.781 151.13,55.423 151.13,56.515 151.515,56.9 U42_UB2.32@153.134,56.9
A_RDC_DOS_UB1: RN12_UB1.1 U42_UB1.35 | length 3.6
  Top Layer w0.254: RN12_UB1.1@95.747,56.667 97.638,56.667 98.105,57.135 U42_UB1.35@99.199,57.135
A_RDC_DOS_UB2: RN12_UB2.1 U42_UB2.35 | length 4.5
  Top Layer w0.254: RN12_UB2.1@149.784,53.181 150.412,53.181 152.044,54.813 152.044,55.22 152.225,55.4 U42_UB2.35@153.134,55.4
A_RDC_FSYNC_UB1: U34_UB1.9 U42_UB1.4 | length 27.4
  Top Layer w0.254: U34_UB1.9@85.674,53.301 89.395,53.301 v1(90.805,54.712) ; v1(104.343,59.842) 104.394,59.842 106.102,58.135 U42_UB1.4@108.399,58.135
  Mid-Layer 2 w0.254: v1(90.805,54.712) 92.481,56.388 92.481,57.861 94.996,60.376 103.81,60.376 v1(104.343,59.842)
A_RDC_FSYNC_UB2: U34_UB2.9 U42_UB2.4 | length 20.5
  Top Layer w0.254: U42_UB2.4@162.334,56.4 163.512,56.4 v1@163.906,56.794 ; v1@175.895,56.134 v1(175.997,56.134) 176.581,56.134 177.267,56.82 179.07,56.82 179.286,57.036 ; 180.061,57.036 179.286,57.036 ; U34_UB2.9@181.178,57.036 179.286,57.036
  Mid-Layer 2 w0.254: v1@163.906,56.794 164.287,56.794 164.922,56.159 175.971,56.159 v1(175.997,56.134)
  other v1: 163.906,56.693
A_RDC_LOT_UB1: RN12_UB1.3 U42_UB1.34 | length 3.5
  Top Layer w0.254: RN12_UB1.3@95.747,57.455 97.778,57.455 97.958,57.635 U42_UB1.34@99.199,57.635
A_RDC_LOT_UB2: RN12_UB2.3 U42_UB2.34 | length 4.4
  Top Layer w0.254: RN12_UB2.3@149.784,53.981 150.335,53.981 151.587,55.233 151.587,55.728 151.759,55.9 152.254,55.9 U42_UB2.34@153.134,55.9
A_RDC_NM_UB1: RN12_UB1.7 U42_UB1.31 | length 3.5
  Top Layer w0.254: RN12_UB1.7@95.747,59.135 U42_UB1.31@99.199,59.135
A_RDC_NM_UB2: RN12_UB2.7 U42_UB2.31 | length 4.7
  Top Layer w0.254: RN12_UB2.7@149.784,55.582 150.324,55.582 150.673,55.931 150.673,56.921 151.151,57.4 U42_UB2.31@153.134,57.4
A_RDC_RES0_UB1: R284_UB1.1 U34_UB1.2 U42_UB1.48 | length 33.4
  Top Layer w0.254: U34_UB1.2@85.674,49.801 90.09,49.801 v1(90.094,49.798) ; U42_UB1.48@106.549,54.785 106.549,55.463 106.585,55.499 110.033,55.499 v1(110.719,54.813) R284_UB1.1@111.851,54.813
  Mid-Layer 2 w0.254: v1(90.094,49.798) 90.26,49.798 92.786,52.324 98.019,52.324 100.508,54.813 v1(110.719,54.813)
A_RDC_RES0_UB2: R284_UB2.1 U34_UB2.2 U42_UB2.48 | length 30.2
  Top Layer w0.254: U42_UB2.48@160.484,53.05 160.484,52.572 160.858,52.197 v1(164.567,52.197) 164.567,51.613 164.926,51.253 R284_UB2.1@165.811,51.253 ; v1@171.704,53.137 171.704,58.903 173.338,60.536 U34_UB2.2@181.178,60.536
  Mid-Layer 2 w0.254: v1(164.567,52.197) 170.739,52.197 171.679,53.137 171.628,53.137 v1(171.577,53.188)
A_RDC_RES1_UB1: R287_UB1.1 U34_UB1.3 U42_UB1.1 | length 30.7
  Top Layer w0.254: U34_UB1.3@85.674,50.301 89.468,50.301 v1(89.891,50.724) ; U42_UB1.1@108.399,56.635 109.913,56.635 v1(110.341,56.207) R287_UB1.1@111.851,56.207
  Mid-Layer 2 w0.254: v1(89.891,50.724) 92.253,53.086 97.231,53.086 99.517,55.372 109.505,55.372 v1(110.341,56.207)
A_RDC_RES1_UB2: R287_UB2.1 U34_UB2.3 U42_UB2.1 | length 26.4
  Top Layer w0.254: U42_UB2.1@162.334,54.9 162.854,54.9 v1(164.592,53.162) 165.397,53.162 R287_UB2.1@165.811,52.748 ; v1@172.441,54.127 172.441,58.445 174.031,60.036 U34_UB2.3@181.178,60.036
  Mid-Layer 2 w0.254: v1(164.592,53.162) 164.744,53.01 169.697,53.01 170.815,54.127 v1(172.415,54.127)
A_RDC_RESET_UB1: R261_UB1.1 U34_UB1.14 U42_UB1.33 | length 18.9
  Top Layer w0.254: U34_UB1.14@85.674,55.801 87.805,55.801 v1@89.599,57.594 ; U42_UB1.33@99.199,58.135 100.629,58.135 v1(100.635,58.141)
  Bottom Layer w0.254: v1@89.586,57.607 90.119,58.141 v1(100.635,58.141) 101.625,58.141 R261_UB1.1@101.981,58.496
  other v1: 89.535,57.607
A_RDC_RESET_UB2: R261_UB2.1 U34_UB2.14 U42_UB2.33 | length 30.6
  Top Layer w0.254: U42_UB2.33@153.134,56.4 154.7,56.4 v1(154.711,56.388) ; v1@176.883,54.536 U34_UB2.14@181.178,54.536
  Mid-Layer 2 w0.254: v1(154.711,56.388) 155.372,55.728 159.156,55.728 159.715,55.169 163.69,55.169 164.071,55.55 175.362,55.55 176.403,54.508 v1(176.86,54.508)
  Bottom Layer w0.254: R261_UB2.1@153.264,56.388 v1(154.711,56.388)
A_RDC_SAMPLE_UB1: R293_UB1.1 U34_UB1.13 U42_UB1.10 | length 36.3
  Top Layer w0.254: U34_UB1.13@85.674,55.301 88.296,55.301 v1@89.903,56.909 ; v1(106.502,60.996) 106.641,61.135 U42_UB1.10@108.399,61.135 109.319,61.135 109.576,61.392 109.576,68.25 111.277,69.952 R293_UB1.1@111.648,69.952
  Mid-Layer 2 w0.254: v1(90.094,57.074) 90.526,57.074 91.288,57.074 91.732,57.518 91.732,58.28 94.412,60.96 v1@106.466,60.96 ; v1@106.466,60.96 v1(106.502,60.996) v1@106.466,60.96
A_RDC_SAMPLE_UB2: R293_UB2.1 U34_UB2.13 U42_UB2.10 | length 31.9
  Top Layer w0.254: U42_UB2.10@162.334,59.4 160.92,59.4 160.731,59.588 160.731,60.401 161.201,60.871 162.039,60.871 162.789,61.62 R293_UB2.1@162.789,65.608 ; v1(176.975,55.512) 177.45,55.036 U34_UB2.13@181.178,55.036
  Mid-Layer 2 w0.254: v1(160.782,59.512) 160.782,59.182 162.306,57.658 164.465,57.658 164.973,57.15 175.978,57.15 176.784,56.344 176.784,55.702 v1(176.975,55.512)
A_RDC_SCLK_UB1: U34_UB1.12 U42_UB1.13 | length 27.6
  Top Layer w0.254: U34_UB1.12@85.674,54.801 89.117,54.801 90.754,56.439 v1(90.754,60.249) ; v1(106.451,62.713) 106.549,62.81 U42_UB1.13@106.549,63.985
  Mid-Layer 2 w0.254: v1(90.754,60.249) 93.218,62.713 v1(106.451,62.713)
A_RDC_SCLK_UB2: U34_UB2.12 U42_UB2.13 | length 25.8
  Top Layer w0.254: U42_UB2.13@160.484,62.25 160.484,61.716 160.579,61.62 v1(161.646,61.62) ; v1(177.698,56.109) 177.749,56.109 178.322,55.536 ; 179.273,55.536 178.322,55.536 ; U34_UB2.12@181.178,55.536 178.322,55.536
  Mid-Layer 2 w0.254: v1(161.646,61.62) 161.646,59.893 162.89,58.649 164.516,58.649 165.354,57.81 175.997,57.81 v1(177.698,56.109)
A_RDC_SDI_UB1: U34_UB1.11 U42_UB1.12 | length 28.2
  Top Layer w0.254: U34_UB1.11@85.674,54.301 89.379,54.301 91.364,56.286 v1(91.364,59.741) ; v1(105.308,62.128) 107.334,62.128 107.34,62.135 ; 107.163,62.135 107.34,62.135 ; U42_UB1.12@108.399,62.135 107.34,62.135
  Mid-Layer 2 w0.254: v1(91.364,59.741) 91.364,59.817 93.675,62.128 v1(105.308,62.128)
A_RDC_SDI_UB2: U34_UB2.11 U42_UB2.12 | length 22.5
  Top Layer w0.254: U42_UB2.12@162.334,60.4 162.838,60.4 v1@163.297,60.858 ; v1@178.6,56.147 178.711,56.036 U34_UB2.11@181.178,56.036
  Mid-Layer 2 w0.254: v1(163.195,60.909) 162.814,60.528 162.814,59.665 163.17,59.309 167.081,59.309 167.97,58.42 176.403,58.42 177.368,57.455 ; 177.381,57.442 177.368,57.455 ; v1(178.613,56.159) 178.613,56.21 177.368,57.455
A_RDC_SDO_UB1: U42_UB1.11 U52_UB1.11 | length 28
  Top Layer w0.254: U52_UB1.11@84.74,64.111 86.206,64.111 87.605,62.713 87.605,60.808 89.002,59.411 v1(89.332,59.411) ; v1(105.893,61.544) 105.983,61.635 U42_UB1.11@108.399,61.635
  Mid-Layer 2 w0.254: v1@89.357,59.385 89.814,58.928 91.542,58.928 94.158,61.544 v1(105.893,61.544)
A_RDC_SDO_UB2: U42_UB2.11 U52_UB2.11 | length 21.1
  Top Layer w0.254: U42_UB2.11@162.789,59.893 v1(163.652,59.893) ; U52_UB2.11@174.848,67.106 176.582,67.106 v1(176.632,67.056)
  Mid-Layer 2 w0.254: v1(163.652,59.893) 172.415,59.893 174.371,61.849 174.371,66.065 175.362,67.056 v1(176.632,67.056)
A_REFOUT: C259_UB1.1 C260_UB1.1 C261_UB1.1 C262_UB1.1 R200_UB1.1 R205_UB1.1 R220_UB1.1 R225_UB1.1 U42_UB1.47 | length 37.5
  Top Layer w0.254: v1(106.502,56.249) 106.049,55.796 U42_UB1.47@106.049,54.785 106.049,53.794 106.35,53.492 107.493,53.492 108.077,54.077 111.074,54.077 112.598,52.553 C259_UB1.1@113.011,52.553
  Top Layer w0.508: v1(107.188,41.631) C261_UB1.1@107.188,42.748 ; R200_UB1.1@108.65,38.506 R200_UB1.1@108.687,38.506 R220_UB1.1@113.233,38.506
  Mid-Layer 1 w1.016: 106.782,56.083 107.188,55.677 v1(107.188,41.631)
  Mid-Layer 2 w1.016: v1(107.188,41.631) 107.188,40.64 109.347,38.481 v1(109.449,38.481)
  Bottom Layer w0.508: v1(106.502,56.249) 106.502,56.388 107.163,57.048 C260_UB1.1@108.56,57.048
A_REFOUT_UB2: C259_UB2.1 C260_UB2.1 C261_UB2.1 C262_UB2.1 R200_UB2.1 R205_UB2.1 R220_UB2.1 R225_UB2.1 U42_UB2.47 | length 28.9
  Top Layer w0.254: U42_UB2.47@159.984,53.05 v1(159.984,54.331)
  Top Layer w0.762: R200_UB2.1@152.451,43.231 R205_UB2.1@154.026,43.231 v1(154.902,43.231) R225_UB2.1@155.778,43.231 157.371,43.231 R220_UB2.1@157.378,43.223
  Mid-Layer 4 w0.508: 159.969,52.934 159.984,52.948 v1(159.984,54.331)
  Mid-Layer 4 w1.016: v1(154.902,43.231) 157.988,43.231 158.674,43.917 158.674,46.406 158.242,46.838 158.242,52.146 158.547,52.451 159.944,52.451 159.995,52.502 159.969,52.527 159.969,52.934
  Bottom Layer w0.508: C260_UB2.1@159.664,55.169 159.984,54.85 v1(159.984,54.331)
  Bottom Layer w0.762: v1(154.902,43.231) C262_UB2.1@156.108,43.231 ; C260_UB2.1@159.664,55.27 C259_UB2.1@162.154,55.27 ; C261_UB2.1@162.281,53.162 162.281,54.94 C259_UB2.1@162.331,54.991
A_SIN+: R197_UB1.1 R200_UB1.2 U5.E3 | length 47.6
  Top Layer w0.254: R197_UB1.1@108.681,42.723 108.687,42.717 v1(108.687,41.3) R200_UB1.2@108.687,40.081 ; U5.E3@110.7,1.373 110.7,2.572 111.455,3.327 111.455,6.858 115.494,10.897 115.494,29.464 v1(111.506,33.452)
  Bottom Layer w0.254: 108.687,40.31 108.687,40.069 ; v1(108.687,41.3) 108.687,40.069 ; v1(111.506,33.452) 110.693,34.265 110.693,38.063 108.687,40.069
A_SIN+'_UB1: C227_UB1.2 R197_UB1.2 U42_UB1.41 | length 12.9
  Top Layer w0.254: U42_UB1.41@103.049,54.785 103.049,53.148 106.274,49.923 106.274,47.981 108.483,45.771 C227_UB1.2@108.661,45.771 108.681,45.751 R197_UB1.2@108.681,44.298
A_SIN+'_UB2: C227_UB2.2 R197_UB2.2 U42_UB2.41 | length 8.6
  Top Layer w0.254: R197_UB2.2@152.451,48.057 C227_UB2.2@152.451,49.649 152.578,49.776 152.578,50.521 152.933,50.876 154.178,50.876 154.965,51.664 156.667,51.664 156.984,51.98 U42_UB2.41@156.984,53.05
A_SIN+_UB2: R197_UB2.1 R200_UB2.2 U5.E8 | length 77.5
  Top Layer w0.254: v1(119.786,30.201) 119.786,7.747 120.955,6.579 120.955,1.628 U5.E8@120.7,1.373 ; R200_UB2.2@152.451,44.806 R197_UB2.1@152.451,46.634
  Mid-Layer 3 w0.381: v1(119.786,30.201) 118.44,31.547 118.44,34.798 119.355,35.712 120.448,35.712 122.568,37.833 ; 122.757,38.021 122.568,37.833 ; v1(152.463,45.695) 152.463,45.148 152.197,44.882 152.07,45.009 148.666,45.009 147.777,44.12 145.644,44.12 144.399,42.875 144.399,41.25 143.535,40.386 141.986,40.386 141.415,40.957 127.67,40.957 125.006,40.957 124.181,40.132 124.181,39.549 124.181,39.445 122.568,37.833
A_SIN-: R205_UB1.2 R213_UB1.1 U5.D3 | length 49.2
  Top Layer w0.254: R213_UB1.1@110.2,42.723 110.211,42.712 v1(110.211,41.326) R205_UB1.2@110.211,40.132 ; U5.D3@110.7,-0.627 111.709,0.382 111.709,2.305 112.344,2.94 112.344,6.375 116.027,10.058 116.027,30.302 v1(112.598,33.731)
  Bottom Layer w0.254: 110.211,39.472 110.211,39.446 ; v1(110.211,41.326) 110.211,39.446 ; v1(112.598,33.731) 112.598,37.059 110.211,39.446
A_SIN-'_UB1: C227_UB1.1 R213_UB1.2 U42_UB1.42 | length 13.8
  Top Layer w0.254: U42_UB1.42@103.549,54.785 103.549,53.449 107.061,49.936 107.061,48.412 108.788,46.685 109.703,46.685 110.236,46.152 C227_UB1.1@110.236,45.771 110.2,45.735 R213_UB1.2@110.2,44.298
A_SIN-'_UB2: C227_UB2.1 R213_UB2.2 U42_UB2.42 | length 7.4
  Top Layer w0.254: R213_UB2.2@154.026,48.049 C227_UB2.1@154.026,49.649 154.026,49.657 155.524,51.156 157.175,51.156 157.484,51.464 U42_UB2.42@157.484,53.05
A_SIN-_UB2: R205_UB2.2 R213_UB2.1 U5.D8 | length 80.1
  Top Layer w0.254: v1(120.193,31.166) 120.574,30.785 120.574,7.925 122.428,6.071 122.428,3.683 121.742,2.997 121.742,0.415 U5.D8@120.7,-0.627 ; R205_UB2.2@154.026,44.806 R213_UB2.1@154.026,46.627
  Mid-Layer 3 w0.381: v1(120.193,31.166) 120.218,31.14 120.218,34.671 120.65,35.103 121.971,35.103 126.009,39.141 128.778,39.141 129.845,40.208 135.509,40.208 136.271,39.446 143.612,39.446 145.313,41.148 145.313,42.723 145.859,43.269 147.256,43.269 147.701,42.824 152.832,42.824 154.013,44.005 v1(154.013,45.695)
ADCINA0_UB1: C355_UB1.2 R298_UB1.1 U55_UB1.42 | length 12.2
  Top Layer w0.254: R298_UB1.1@37.567,84.684 37.567,84.435 39.68,82.321 41.442,82.321 42.04,81.723 U55_UB1.42@42.04,80.391 42.04,79.202 41.3,78.462 v1(41.3,77.419)
  Bottom Layer w0.254: C355_UB1.2@40.742,75.844 40.742,76.86 v1@41.25,77.368
  other v1: 37.059,84.734
ADCINA0_UB2: C355_UB2.2 R298_UB2.1 U55_UB2.42 | length 10.5
  Top Layer w0.254: R298_UB2.1@194.869,84.912 197.079,82.702 198.526,82.702 198.885,82.344 U55_UB2.42@198.885,80.696 198.885,79.734 v1(197.561,78.41)
  Bottom Layer w0.254: C355_UB2.2@197.561,77.521 v1(197.561,78.41)
ADCINA1_UB1: C361_UB1.2 R301_UB1.1 U55_UB1.41 | length 10.7
  Top Layer w0.254: R301_UB1.1@38.989,84.684 38.989,84.43 40.538,82.88 41.834,82.88 42.54,82.174 U55_UB1.41@42.54,80.391 42.54,79.015 41.91,78.384 v1@41.91,78.156
  Bottom Layer w0.254: C361_UB1.2@41.072,79.299 41.91,78.461 v1(41.91,78.003)
ADCINA1_UB2: C361_UB2.2 R301_UB2.1 U55_UB2.41 | length 9.5
  Top Layer w0.254: R301_UB2.1@196.297,84.887 196.297,84.551 197.637,83.21 198.933,83.21 199.385,82.758 U55_UB2.41@199.385,80.696 199.385,78.811 v1(198.984,78.41)
  Bottom Layer w0.254: C361_UB2.2@198.984,77.546 v1(198.984,78.41)
ADCINA2_UB1: C372_UB1.2 R305_UB1.1 U55_UB1.40 | length 10.7
  Top Layer w0.254: R305_UB1.1@40.386,84.684 40.386,84.348 41.371,83.363 42.189,83.363 43.04,82.512 U55_UB1.40@43.04,80.391 43.04,78.854 42.57,78.384 v1(42.57,77.597)
  Bottom Layer w0.254: C372_UB1.2@42.24,75.844 42.24,77.267 v1(42.57,77.597)
ADCINA2_UB2: C372_UB2.2 R305_UB2.1 U55_UB2.40 | length 11.4
  Top Layer w0.254: R305_UB2.1@197.714,84.887 197.714,84.201 198.171,83.744 199.161,83.744 199.885,83.02 U55_UB2.40@199.885,80.696 199.885,78.448 v1(199.873,78.435)
  Bottom Layer w0.254: v1(199.873,78.435) 200.254,78.054 C372_UB2.2@200.254,75.108
ADCINA3_UB1: C354_UB1.2 R297_UB1.1 U55_UB1.39 | length 8.7
  Top Layer w0.254: R297_UB1.1@41.783,84.684 41.783,84.43 43.54,82.672 U55_UB1.39@43.54,80.391 v1@43.54,78.191
  Bottom Layer w0.254: C354_UB1.2@42.621,79.35 42.621,78.816 v1(43.307,78.13)
ADCINA3_UB2: C354_UB2.2 R297_UB2.1 U55_UB2.39 | length 8.4
  Top Layer w0.254: R297_UB2.1@199.136,84.861 199.136,84.582 200.385,83.333 U55_UB2.39@200.385,80.696 200.385,78.82 200.914,78.292 v1(200.914,78.13)
  Bottom Layer w0.254: v1(200.914,78.13) C354_UB2.2@201.549,77.495
ADCINA4_UB1: C360_UB1.2 R300_UB1.1 U55_UB1.38 | length 9.4
  Top Layer w0.254: R300_UB1.1@43.18,84.684 43.18,83.82 44.04,82.96 U55_UB1.38@44.04,80.391 44.04,77.67 43.901,77.531 v1(43.764,77.531)
  Bottom Layer w0.254: C360_UB1.2@43.713,75.87 43.713,77.48 v1(43.764,77.531)
ADCINA4_UB2: C360_UB2.2 R300_UB2.1 U55_UB2.38 | length 11.1
  Top Layer w0.254: R300_UB2.1@200.558,84.861 200.635,84.785 200.635,83.947 200.885,83.696 U55_UB2.38@200.885,80.696 200.885,79.048 201.676,78.257 201.676,77.14 202.413,76.403 v1(202.667,76.403)
  Bottom Layer w0.254: C360_UB2.2@202.667,74.752 v1(202.667,76.403)
ADCINA5_UB1: C371_UB1.2 R304_UB1.1 U55_UB1.37 | length 10
  Top Layer w0.254: v1(44.45,77.14) 44.54,77.14 U55_UB1.37@44.54,80.391 44.54,84.647 R304_UB1.1@44.577,84.684
  Bottom Layer w0.254: C371_UB1.2@44.145,79.35 44.45,79.045 v1(44.45,77.14)
ADCINA5_UB2: C371_UB2.2 R304_UB2.1 U55_UB2.37 | length 9.4
  Top Layer w0.254: R304_UB2.1@201.981,84.861 201.981,84.15 201.385,83.555 U55_UB2.37@201.385,80.696 201.385,79.234 v1@202.873,77.746
  Bottom Layer w0.254: v1(202.768,77.641) 203.918,77.641 203.886,77.673 C371_UB2.2@203.886,77.445
ADCINA6_UB1: C1_UB1.2 R3_UB1.1 U55_UB1.36 | length 9.4
  Top Layer w0.254: v1(45.314,77.14) 45.28,77.14 45.009,77.411 45.009,80.36 U55_UB1.36@45.04,80.391 45.04,83.369 45.999,84.328 R3_UB1.1@45.999,84.684
  Bottom Layer w0.254: C1_UB1.2@45.212,75.87 45.212,77.038 v1(45.314,77.14)
ADCINA6_UB2: C1_UB2.2 R3_UB2.1 U55_UB2.36 | length 12.8
  Top Layer w0.254: R3_UB2.1@203.403,84.861 203.403,84.506 201.885,82.988 U55_UB2.36@201.885,80.696 201.885,79.445 203.53,77.8 v1(204.902,77.8)
  Bottom Layer w0.254: v1(204.902,77.8) 205.054,77.648 C1_UB2.2@205.054,74.803
ADCINA7_UB1: C2_UB1.2 R4_UB1.1 U55_UB1.35 | length 9.3
  Top Layer w0.254: v1@45.54,77.978 U55_UB1.35@45.54,80.391 45.54,82.929 46.126,83.515 46.838,83.515 47.396,84.074 R4_UB1.1@47.396,84.684
  Bottom Layer w0.254: v1(45.593,77.978) C2_UB1.2@45.593,79.375
ADCINA7_UB2: C2_UB2.2 R4_UB2.1 U55_UB2.35 | length 11.1
  Top Layer w0.254: R4_UB2.1@204.826,84.861 204.826,84.746 202.385,82.306 U55_UB2.35@202.385,80.696 202.385,79.623 203.573,78.435 v1(205.511,78.435)
  Bottom Layer w0.254: v1(205.511,78.435) 206.299,77.648 C2_UB2.2@206.299,77.546
ADCINB0_UB1: U55_UB1.46
ADCINB0_UB2: U55_UB2.46
ADCINB1_UB1: U55_UB1.47
ADCINB1_UB2: U55_UB2.47
ADCINB2_UB1: U55_UB1.48
ADCINB2_UB2: U55_UB2.48
ADCINB3_UB1: U55_UB1.49
ADCINB3_UB2: U55_UB2.49
ADCINB4_UB1: U55_UB1.50
ADCINB4_UB2: U55_UB2.50
ADCINB5_UB1: U55_UB1.51
ADCINB5_UB2: U55_UB2.51
ADCINB6_UB1: U55_UB1.52
ADCINB6_UB2: U55_UB2.52
ADCINB7_UB1: U55_UB1.53
ADCINB7_UB2: U55_UB2.53
ADCLO_UB1: R328_UB1.2 U55_UB1.43 | length 3.7
  Top Layer w0.254: v1@40.627,78.549 41.54,79.462 U55_UB1.43@41.54,80.391
  Bottom Layer w0.254: R328_UB1.2@39.548,79.223 39.649,79.223 40.538,78.334 v1(40.665,78.334)
ADCLO_UB2: R328_UB2.2 U55_UB2.43 | length 7.5
  Top Layer w0.254: R328_UB2.2@193.421,84.887 193.421,84.684 195.885,82.22 198.069,82.22 198.385,81.904 U55_UB2.43@198.385,80.696
ADCREFIN_UB1: C392_UB1.1 U55_UB1.54 | length 7.4
  Top Layer w0.254: v1(35.789,77.14) 36.424,77.14 36.855,76.708 36.855,74.219 37.383,73.691 U55_UB1.54@38.84,73.691
  Bottom Layer w0.254: C392_UB1.1@34.341,77.114 35.763,77.114 v1(35.789,77.14)
ADCREFIN_UB2: C392_UB2.1 U55_UB2.54 | length 8.5
  Top Layer w0.254: C392_UB2.1@190.348,77.419 191.135,77.419 ; C392_UB2.1@190.348,77.648 190.906,77.648 191.135,77.419 ; U55_UB2.54@195.685,73.996 194.558,73.996 194.183,74.371 194.183,75.184 193.573,75.794 192.075,75.794 191.4,76.469 191.4,77.154 191.135,77.419
ADCREFM_UB1: C382_UB1.1 C389_UB1.1 U55_UB1.55 | length 9.2
  Top Layer w0.254: C382_UB1.1@33.409,76.2 33.892,75.717 35.992,75.717 36.271,75.438 36.271,73.635 36.715,73.191 U55_UB1.55@38.84,73.191
  Bottom Layer w0.254: C389_UB1.1@34.341,75.565 35.636,75.565 v1(35.763,75.692)
ADCREFM_UB2: C382_UB2.1 C389_UB2.1 U55_UB2.55 | length 6.4
  Top Layer w0.254: C382_UB2.1@192.075,74.295 C382_UB2.1@192.087,74.283 ; C382_UB2.1@192.253,74.117 192.874,73.496 U55_UB2.55@195.685,73.496
  Top Layer w0.762: C389_UB2.1@190.348,76.251 192.075,74.524 C382_UB2.1@192.075,74.295
ADCREFP_UB1: C380_UB1.1 C381_UB1.1 U55_UB1.56 | length 7.5
  Top Layer w0.254: C381_UB1.1@33.409,73.66 35.357,73.66 v1(35.712,73.304) 36.326,72.691 U55_UB1.56@38.84,72.691
  Bottom Layer w0.254: C380_UB1.1@34.417,74.117 34.9,74.117 v1(35.712,73.304)
ADCREFP_UB2: C380_UB2.1 C381_UB2.1 U55_UB2.56 | length 7.8
  Top Layer w0.254: C381_UB2.1@191.745,72.415 C381_UB2.1@192.532,72.415 ; C381_UB2.1@192.532,71.628 192.532,72.314 193.214,72.996 U55_UB2.56@195.685,72.996
  Top Layer w0.762: C380_UB2.1@190.322,69.926 190.83,69.926 192.1,71.196 C381_UB2.1@192.1,71.831
ADCREXT_UB1: R325_UB1.2 U55_UB1.57 | length 4.6
  Top Layer w0.254: v1@35.738,72.263 35.81,72.191 U55_UB1.57@38.84,72.191
  Bottom Layer w0.254: R325_UB1.2@34.341,72.568 35.382,72.568 35.509,72.441 v1(35.738,72.441)
ADCREXT_UB2: R325_UB2.2 U55_UB2.57 | length 2.3
  Top Layer w0.254: U55_UB2.57@195.758,72.492 v1@197.154,72.492
  Bottom Layer w0.508: v1(197.155,72.466) R325_UB2.2@197.155,73.381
